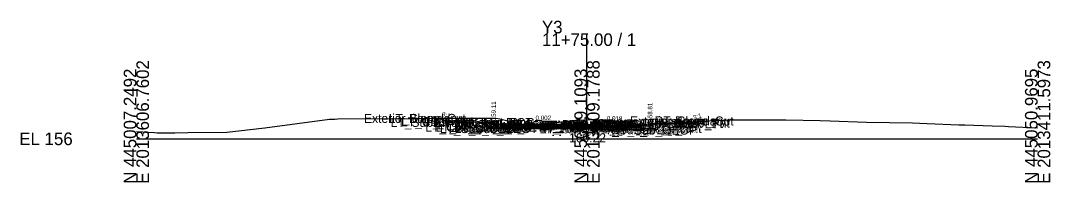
# Model space of a CAD drawing. Extents: x -26 to 203, y -10 to 5017.
# Drawn here: x -25.7 to 202.8, y 3490.3 to 3526.3 of the extents above; entities that cross this region are included whole.
import ezdxf

# ---------------------------------------------------------------- set-up
doc = ezdxf.new("R2010")
doc.units = 0
for name, color, linetype in [('Default', 7, 'Continuous'), ('Exist Cross Section Cell', 7, 'Continuous'), ('Exist XS Center Line Elevation Label', 7, 'Continuous'), ('Exist XS Ground Line', 7, 'Continuous'), ('Prop CMT Conc Surface', 7, 'Continuous'), ('Prop CMT Concrete Structures', 7, 'Continuous'), ('Prop CMT Pvmt Course 1', 7, 'Continuous'), ('Prop CMT Pvmt Course 1 CG', 7, 'Continuous'), ('Prop CMT Pvmt Course 2', 7, 'Continuous'), ('Prop CMT Pvmt Course 3', 7, 'Continuous'), ('Prop CMT Pvmt Surface', 7, 'Continuous'), ('Prop CMT Slope Grass', 7, 'Continuous'), ('Prop CMT Subgrade Earthwork', 7, 'Continuous'), ('Prop XS Earthwork Shape', 7, 'Continuous'), ('Prop XS Hydro Elevations', 7, 'Continuous'), ('Prop XS SE Text', 7, 'Continuous'), ('Prop XS Side Slope Text', 7, 'Continuous'), ('Scratch_Level_0', 7, 'Continuous')]:
    doc.layers.add(name, color=color, linetype=linetype)

msp = doc.modelspace()

# ---------------------------------------------------------------- linework, layer by layer
at = {"layer": 'Exist Cross Section Cell'}
for p, q in [((100, 3500), (100, 3523.44)), ((0, 3500), (100, 3500)), ((100, 3500), (200, 3500))]:
    msp.add_line(p, q, dxfattribs=at)
at = {"layer": 'Exist XS Ground Line'}
msp.add_lwpolyline([(0, 3501.62), (1.4, 3501.54), (2, 3501.51), (2.61, 3501.48), (3.99, 3501.38), (4.62, 3501.34), (4.93, 3501.32), (8.56, 3501.35), (11.44, 3501.37), (20.11, 3501.46), (28.49, 3502.45), (42.89, 3504.38), (43.66, 3504.4), (44.07, 3504.4), (44.69, 3504.41), (62.05, 3504.53), (66.62, 3504.6), (73.3, 3504.59), (79.57, 3504.57), (80.3, 3504.51), (85.94, 3503.2), (86.79, 3503.08), (87.59, 3502.9), (96.64, 3504.04), (100, 3504.22), (101.72, 3504.31), (105.87, 3504.06), (112.36, 3503.15), (113.04, 3503.27), (113.62, 3503.35), (119.14, 3503.57), (119.74, 3503.64), (124.42, 3503.83), (131.25, 3504.23), (140.74, 3504.24), (141.5, 3504.25), (144.13, 3504.22), (151.75, 3504.05), (153.94, 3504), (162, 3503.72), (167.15, 3503.65), (172.24, 3503.57), (175.47, 3503.38), (182.49, 3503.14), (183.85, 3503.09), (189.88, 3502.88), (192.74, 3502.78), (193.57, 3502.74), (200, 3502.46)], dxfattribs=at)
at = {"layer": 'Prop CMT Conc Surface'}
for points in [[(79.28, 3503.11), (79.28, 3503.61), (78.78, 3503.61)], [(81.28, 3503.19), (79.28, 3503.11)], [(112, 3502.93), (114, 3502.81)], [(114, 3502.81), (114, 3503.31), (114.5, 3503.31)]]:
    msp.add_lwpolyline(points, dxfattribs=at)
at = {"layer": 'Prop CMT Concrete Structures'}
for points in [[(81.28, 3503.19), (79.28, 3503.11), (79.28, 3503.61), (78.78, 3503.61)], [(78.78, 3503.61), (78.78, 3502.61), (81.28, 3502.61)], [(81.28, 3502.61), (81.28, 3503.19)], [(112, 3502.93), (114, 3502.81), (114, 3503.31), (114.5, 3503.31)], [(114.5, 3503.31), (114.5, 3502.3), (112, 3502.35)], [(112, 3502.35), (112, 3502.93)]]:
    msp.add_lwpolyline(points, dxfattribs=at)
at = {"layer": 'Prop CMT Pvmt Course 1'}
for points in [[(100, 3503.15), (81.28, 3503.19)], [(81.28, 3503.19), (81.28, 3502.94)], [(81.28, 3502.94), (100, 3502.9)], [(100, 3502.9), (100, 3503.15)], [(100, 3503.15), (112, 3502.93)], [(100, 3502.9), (100, 3503.15)], [(112, 3502.68), (100, 3502.9)], [(112, 3502.93), (112, 3502.68)]]:
    msp.add_lwpolyline(points, dxfattribs=at)
msp.add_lwpolyline([(100, 3502.9), (100, 3503.02), (100, 3503.02), (100, 3502.9)], close=True, dxfattribs=at)
msp.add_lwpolyline([(100, 3502.9), (100, 3503.02), (100, 3503.02), (100, 3502.9)], close=True, dxfattribs=at)
at = {"layer": 'Prop CMT Pvmt Course 1 CG'}
for points in [[(81.28, 3502.61), (78.28, 3502.61), (77.94, 3502.28)], [(77.94, 3502.28), (81.28, 3502.27)], [(81.28, 3502.27), (81.28, 3502.61)], [(112, 3502.35), (115, 3502.29), (115.34, 3501.95)], [(112, 3502.01), (112, 3502.35)], [(115.34, 3501.95), (112, 3502.01)]]:
    msp.add_lwpolyline(points, dxfattribs=at)
at = {"layer": 'Prop CMT Pvmt Course 2'}
for points in [[(100, 3502.9), (81.28, 3502.94)], [(81.28, 3502.94), (81.28, 3502.61)], [(81.28, 3502.61), (100, 3502.57)], [(100, 3502.57), (100, 3502.9)], [(100, 3502.57), (100, 3502.9)], [(100, 3502.9), (112, 3502.68)], [(112, 3502.35), (100, 3502.57)], [(112, 3502.68), (112, 3502.35)]]:
    msp.add_lwpolyline(points, dxfattribs=at)
at = {"layer": 'Prop CMT Pvmt Course 3'}
for points in [[(100, 3502.57), (81.28, 3502.61)], [(81.28, 3502.61), (81.28, 3502.27)], [(81.28, 3502.27), (100, 3502.23)], [(100, 3502.23), (100, 3502.57)], [(100, 3502.57), (112, 3502.35)], [(100, 3502.23), (100, 3502.57)], [(112, 3502.01), (100, 3502.23)], [(112, 3502.35), (112, 3502.01)]]:
    msp.add_lwpolyline(points, dxfattribs=at)
at = {"layer": 'Prop CMT Pvmt Surface'}
for points in [[(100, 3503.15), (81.28, 3503.19)], [(100, 3503.15), (112, 3502.93)]]:
    msp.add_lwpolyline(points, dxfattribs=at)
at = {"layer": 'Prop CMT Slope Grass'}
for points in [[(78.78, 3503.61), (69.28, 3503.8), (66.89, 3504.6)], [(114.5, 3503.31), (124, 3503.5), (125.11, 3503.87)]]:
    msp.add_lwpolyline(points, dxfattribs=at)
at = {"layer": 'Prop CMT Subgrade Earthwork'}
for points in [[(81.28, 3502.27), (77.94, 3502.28), (76.57, 3503.66)], [(100, 3502.23), (81.28, 3502.27)], [(100, 3502.23), (112, 3502.01)], [(112, 3502.01), (115.34, 3501.95), (116.75, 3503.36)]]:
    msp.add_lwpolyline(points, dxfattribs=at)
at = {"layer": 'Prop XS Earthwork Shape'}
for points in [[(79.57, 3504.57), (80.3, 3504.51), (85.94, 3503.2), (86.11, 3503.18), (81.28, 3503.19), (79.28, 3503.11), (79.28, 3503.61), (78.78, 3503.61), (76.57, 3503.66), (69.28, 3503.8), (66.89, 3504.6), (73.3, 3504.59)], [(114.5, 3503.31), (116.75, 3503.36), (115.34, 3501.95), (112, 3502.01), (100, 3502.23), (81.28, 3502.27), (77.94, 3502.28), (76.57, 3503.66), (78.78, 3503.61), (78.78, 3502.61), (81.28, 3502.61), (81.28, 3503.19), (86.11, 3503.18), (86.79, 3503.08), (87.59, 3502.9), (89.77, 3503.17), (100, 3503.15), (112, 3502.93), (112, 3502.35), (114.5, 3502.3)], [(79.28, 3503.61), (78.78, 3503.61), (78.78, 3502.61), (81.28, 3502.61), (81.28, 3503.19), (79.28, 3503.11)], [(112.36, 3503.15), (113.04, 3503.27), (113.62, 3503.35), (119.14, 3503.57), (119.74, 3503.64), (124.42, 3503.83), (125.11, 3503.87), (124, 3503.5), (116.75, 3503.36), (114.5, 3503.31), (114, 3503.31), (114, 3502.81), (112, 3502.93), (100, 3503.15), (89.77, 3503.17), (96.64, 3504.04), (100, 3504.22), (101.72, 3504.31), (105.87, 3504.06)], [(112, 3502.35), (112, 3502.93), (114, 3502.81), (114, 3503.31), (114.5, 3503.31), (114.5, 3502.3)]]:
    msp.add_lwpolyline(points, close=True, dxfattribs=at)

# ---------------------------------------------------------------- texts
at = {"layer": 'Default'}
msp.add_text('-', height=0.0001, dxfattribs=at).set_placement((0, 3500))
at = {"layer": 'Exist Cross Section Cell'}
for s, p in [('Y3', (90, 3523.44)), ('11+75.00 / 1', (90, 3520.64)), ('EL 156', (-26, 3498.6))]:
    msp.add_text(s, height=2.8, dxfattribs=at).set_placement(p)
for s, p in [('E 2013606.7602', (2.8, 3490)), ('E 2013509.1788', (102.8, 3490)), ('E 2013411.5973', (202.8, 3490)), ('N 445007.2492', (0, 3490)), ('N 445029.1093', (100, 3490)), ('N 445050.9695', (200, 3490))]:
    msp.add_text(s, height=2.8, rotation=90, dxfattribs=at).set_placement(p)
at = {"layer": 'Exist XS Center Line Elevation Label'}
msp.add_text('160.22', height=2, dxfattribs=at).set_placement((96.03, 3499.22))
at = {"layer": 'Prop XS Hydro Elevations'}
for s, p in [('159.11', (79.78, 3504.11)), ('158.81', (114.5, 3503.81))]:
    msp.add_text(s, height=1, rotation=90, dxfattribs=at).set_placement(p)
at = {"layer": 'Prop XS SE Text'}
for s, rotation, p in [('0.002', 359.878, (88.58, 3504.17)), ('0.018', 358.9565, (104.4, 3504.07))]:
    msp.add_text(s, height=1, rotation=rotation, dxfattribs=at).set_placement(p)
at = {"layer": 'Prop XS Side Slope Text'}
for rotation, p in [(341.5652, (67.66, 3505.13)), (18.4332, (123.72, 3504.2))]:
    msp.add_text('3:1', height=1, rotation=rotation, dxfattribs=at).set_placement(p)
at = {"layer": 'Scratch_Level_0'}
for s, p in [('Exterior Boundary', (50.52, 3503.54)), ('LT_Slope_Cut', (56.02, 3503.54)), ('LT_Sub_Trench_Out_DLT', (56.44, 3502.66)), ('LT_CSLP_Pnt', (58.75, 3502.8)), ('LT_CG1_Shelf_Out', (64.13, 3501.61)), ('LT_CG_Top_Face', (65.84, 3502.61)), ('LT_CG_Top_BOC', (66.36, 3502.61)), ('LT_CG_Bot_BOC', (66.39, 3501.61)), ('LT_CG_Top_Gut', (66.82, 3502.11)), ('LT_CG_Bot_IE', (70.49, 3501.61)), ('LT_PV2_OEOT', (70.75, 3501.94)), ('LT_PV3_OEOT', (70.75, 3501.61)), ('LT_PV1_OEOT', (71.32, 3502.19)), ('RT_PV2_OEEOP', (89.26, 3501.9)), ('RT_PV3_OEEOP', (89.26, 3501.57)), ('LT_PV2_OEEOP', (89.31, 3501.9)), ('LT_PV3_OEEOP', (89.31, 3501.57)), ('RT_PV1_OEEOP', (89.83, 3502.02)), ('LT_PV1_OEEOP', (89.87, 3502.02)), ('RT_PV2_IEEOP', (89.91, 3501.9)), ('LT_PV2_IEEOP', (89.95, 3501.9)), ('RT_PV1_IEEOP', (90.47, 3502.02)), ('LT_PV1_IEEOP', (90.52, 3502.02)), ('PV2_PGL', (93.91, 3501.9)), ('PV1_PGL', (94.47, 3502.15)), ('RT_Sub_Trench_Out_DLT', (97.27, 3502.36)), ('RT_CG_Top_Face', (101.21, 3502.31)), ('RT_PV2_OEOT', (102.13, 3501.68)), ('RT_CG_Top_Gut', (102.19, 3501.81)), ('RT_PV1_OEOT', (102.69, 3501.93)), ('RT_CG_Top_BOC', (102.74, 3502.31)), ('Exterior Boundary', (109.55, 3502.97)), ('RT_CSLP_Pnt', (114.13, 3502.5)), ('RT_Slope_Cut', (115, 3502.97)), ('LT_Sub_OEOP', (67.36, 3501.28)), ('LT_Sub_OEOT', (70.66, 3501.27)), ('RT_Sub_OEEOP', (89.17, 3501.23)), ('LT_Sub_OEEOP', (89.21, 3501.23)), ('RT_CG1_Shelf_Out', (101.5, 3501.29)), ('RT_CG_Bot_IE', (101.87, 3501.35)), ('RT_Sub_OEOT', (102.03, 3501.01)), ('RT_PV3_OEOT', (102.13, 3501.35)), ('RT_CG_Bot_BOC', (102.77, 3501.3)), ('RT_Sub_OEOP', (105.4, 3500.95))]:
    msp.add_text(s, height=2, dxfattribs=at).set_placement(p)

doc.saveas('drawing.dxf')
